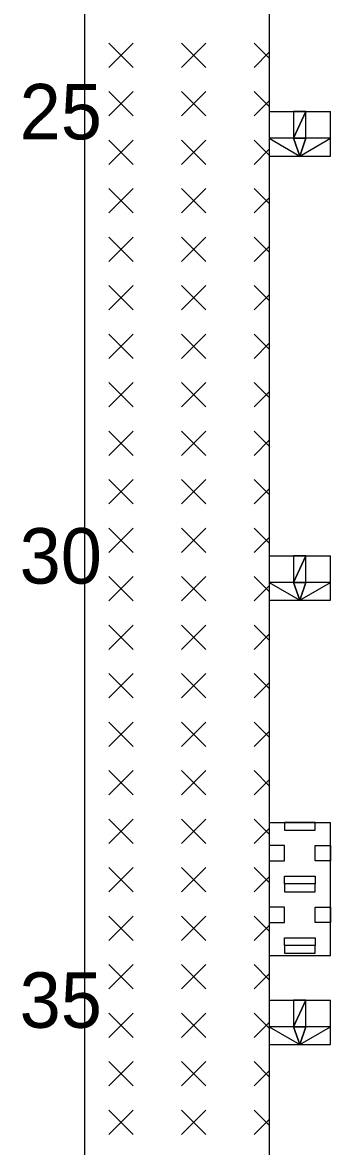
# Model space of a CAD drawing. Extents: x 2150148.6 to 2150220.1, y 143803.7 to 143875.1.
# Drawn here: x 2150202.318 to 2150203.153, y 143849.651 to 143852.692 of the extents above; entities that cross this region are included whole.
import ezdxf

# ---------------------------------------------------------------- set-up
doc = ezdxf.new("R2010")
doc.units = 0
doc.layers.add('Default', color=7, linetype='Continuous')

msp = doc.modelspace()

# ---------------------------------------------------------------- linework, layer by layer
at = {"layer": 'Default'}
for points in [[(2150202.4866, 143858.3678), (2150202.4866, 143846.4416)], [(2150202.9866, 143858.3606), (2150202.9866, 143846.4416)], [(2150202.6178, 143852.6367), (2150202.5522, 143852.5711)], [(2150202.5522, 143852.6367), (2150202.6178, 143852.5711)], [(2150202.8147, 143852.6367), (2150202.749, 143852.5711)], [(2150202.749, 143852.6367), (2150202.8147, 143852.5711)], [(2150202.9459, 143852.6367), (2150202.9866, 143852.596)], [(2150202.9866, 143852.6118), (2150202.9459, 143852.5711)], [(2150202.6178, 143852.5055), (2150202.5522, 143852.4399)], [(2150202.5522, 143852.5055), (2150202.6178, 143852.4399)], [(2150202.8147, 143852.5055), (2150202.749, 143852.4399)], [(2150202.749, 143852.5055), (2150202.8147, 143852.4399)], [(2150202.9459, 143852.5055), (2150202.9866, 143852.4648)], [(2150202.9866, 143852.4805), (2150202.9459, 143852.4399)], [(2150202.9866, 143852.4512), (2150203.1532, 143852.4512)], [(2150203.1532, 143852.331), (2150203.1532, 143852.4512)], [(2150202.6178, 143852.3742), (2150202.5522, 143852.3086)], [(2150202.5522, 143852.3742), (2150202.6178, 143852.3086)], [(2150202.8147, 143852.3742), (2150202.749, 143852.3086)], [(2150202.749, 143852.3742), (2150202.8147, 143852.3086)], [(2150202.9459, 143852.3742), (2150202.9866, 143852.3336)], [(2150202.9866, 143852.3493), (2150202.9459, 143852.3086)], [(2150202.9866, 143852.331), (2150203.1532, 143852.331)], [(2150202.6178, 143852.243), (2150202.5522, 143852.1774)], [(2150202.5522, 143852.243), (2150202.6178, 143852.1774)], [(2150202.8147, 143852.243), (2150202.749, 143852.1774)], [(2150202.749, 143852.243), (2150202.8147, 143852.1774)], [(2150202.9459, 143852.243), (2150202.9866, 143852.2023)], [(2150202.9866, 143852.2181), (2150202.9459, 143852.1774)], [(2150202.6178, 143852.1118), (2150202.5522, 143852.0462)], [(2150202.5522, 143852.1118), (2150202.6178, 143852.0462)], [(2150202.8147, 143852.1118), (2150202.749, 143852.0462)], [(2150202.749, 143852.1118), (2150202.8147, 143852.0462)], [(2150202.9459, 143852.1118), (2150202.9866, 143852.0711)], [(2150202.9866, 143852.0868), (2150202.9459, 143852.0462)], [(2150202.6178, 143851.9805), (2150202.5522, 143851.9149)], [(2150202.5522, 143851.9805), (2150202.6178, 143851.9149)], [(2150202.8147, 143851.9805), (2150202.749, 143851.9149)], [(2150202.749, 143851.9805), (2150202.8147, 143851.9149)], [(2150202.9459, 143851.9805), (2150202.9866, 143851.9399)], [(2150202.9866, 143851.9556), (2150202.9459, 143851.9149)], [(2150202.6178, 143851.8493), (2150202.5522, 143851.7837)], [(2150202.5522, 143851.8493), (2150202.6178, 143851.7837)], [(2150202.8147, 143851.8493), (2150202.749, 143851.7837)], [(2150202.749, 143851.8493), (2150202.8147, 143851.7837)], [(2150202.9459, 143851.8493), (2150202.9866, 143851.8086)], [(2150202.9866, 143851.8244), (2150202.9459, 143851.7837)], [(2150202.6178, 143851.7181), (2150202.5522, 143851.6525)], [(2150202.5522, 143851.7181), (2150202.6178, 143851.6525)], [(2150202.8147, 143851.7181), (2150202.749, 143851.6525)], [(2150202.749, 143851.7181), (2150202.8147, 143851.6525)], [(2150202.9459, 143851.7181), (2150202.9866, 143851.6774)], [(2150202.9866, 143851.6931), (2150202.9459, 143851.6525)], [(2150202.6178, 143851.5868), (2150202.5522, 143851.5212)], [(2150202.5522, 143851.5868), (2150202.6178, 143851.5212)], [(2150202.8147, 143851.5868), (2150202.749, 143851.5212)], [(2150202.749, 143851.5868), (2150202.8147, 143851.5212)], [(2150202.9459, 143851.5868), (2150202.9866, 143851.5462)], [(2150202.9866, 143851.5619), (2150202.9459, 143851.5212)], [(2150202.6178, 143851.4556), (2150202.5522, 143851.39)], [(2150202.5522, 143851.4556), (2150202.6178, 143851.39)], [(2150202.8147, 143851.4556), (2150202.749, 143851.39)], [(2150202.749, 143851.4556), (2150202.8147, 143851.39)], [(2150202.9459, 143851.4556), (2150202.9866, 143851.4149)], [(2150202.9866, 143851.4307), (2150202.9459, 143851.39)], [(2150202.6178, 143851.3244), (2150202.5522, 143851.2588)], [(2150202.5522, 143851.3244), (2150202.6178, 143851.2588)], [(2150202.8147, 143851.3244), (2150202.749, 143851.2588)], [(2150202.749, 143851.3244), (2150202.8147, 143851.2588)], [(2150202.9459, 143851.3244), (2150202.9866, 143851.2837)], [(2150202.9866, 143851.2994), (2150202.9459, 143851.2588)], [(2150202.9866, 143851.2493), (2150203.1532, 143851.2493)], [(2150203.1532, 143851.1291), (2150203.1532, 143851.2493)], [(2150202.6178, 143851.1931), (2150202.5522, 143851.1275)], [(2150202.5522, 143851.1931), (2150202.6178, 143851.1275)], [(2150202.8147, 143851.1931), (2150202.749, 143851.1275)], [(2150202.749, 143851.1931), (2150202.8147, 143851.1275)], [(2150202.9459, 143851.1931), (2150202.9866, 143851.1525)], [(2150202.9866, 143851.1682), (2150202.9459, 143851.1275)], [(2150202.9866, 143851.1291), (2150203.1532, 143851.1291)], [(2150202.6178, 143851.0619), (2150202.5522, 143850.9963)], [(2150202.5522, 143851.0619), (2150202.6178, 143850.9963)], [(2150202.8147, 143851.0619), (2150202.749, 143850.9963)], [(2150202.749, 143851.0619), (2150202.8147, 143850.9963)], [(2150202.9459, 143851.0619), (2150202.9866, 143851.0212)], [(2150202.9866, 143851.037), (2150202.9459, 143850.9963)], [(2150202.6178, 143850.9307), (2150202.5522, 143850.8651)], [(2150202.5522, 143850.9307), (2150202.6178, 143850.8651)], [(2150202.8147, 143850.9307), (2150202.749, 143850.8651)], [(2150202.749, 143850.9307), (2150202.8147, 143850.8651)], [(2150202.9459, 143850.9307), (2150202.9866, 143850.89)], [(2150202.9866, 143850.9057), (2150202.9459, 143850.8651)], [(2150202.6178, 143850.7994), (2150202.5522, 143850.7338)], [(2150202.5522, 143850.7994), (2150202.6178, 143850.7338)], [(2150202.8147, 143850.7994), (2150202.749, 143850.7338)], [(2150202.749, 143850.7994), (2150202.8147, 143850.7338)], [(2150202.9459, 143850.7994), (2150202.9866, 143850.7588)], [(2150202.9866, 143850.7745), (2150202.9459, 143850.7338)], [(2150202.6178, 143850.6682), (2150202.5522, 143850.6026)], [(2150202.5522, 143850.6682), (2150202.6178, 143850.6026)], [(2150202.8147, 143850.6682), (2150202.749, 143850.6026)], [(2150202.749, 143850.6682), (2150202.8147, 143850.6026)], [(2150202.9459, 143850.6682), (2150202.9866, 143850.6275)], [(2150202.9866, 143850.6433), (2150202.9459, 143850.6026)], [(2150202.6178, 143850.537), (2150202.5522, 143850.4714)], [(2150202.5522, 143850.537), (2150202.6178, 143850.4714)], [(2150202.8147, 143850.537), (2150202.749, 143850.4714)], [(2150202.749, 143850.537), (2150202.8147, 143850.4714)], [(2150202.9459, 143850.537), (2150202.9866, 143850.4963)], [(2150202.9866, 143850.5281), (2150203.1532, 143850.5281)], [(2150203.1532, 143850.1676), (2150203.1532, 143850.5281)], [(2150202.9866, 143850.512), (2150202.9459, 143850.4714)], [(2150202.6178, 143850.4057), (2150202.5522, 143850.3401)], [(2150202.5522, 143850.4057), (2150202.6178, 143850.3401)], [(2150202.8147, 143850.4057), (2150202.749, 143850.3401)], [(2150202.749, 143850.4057), (2150202.8147, 143850.3401)], [(2150202.9459, 143850.4057), (2150202.9866, 143850.3651)], [(2150202.9866, 143850.3808), (2150202.9459, 143850.3401)], [(2150202.6178, 143850.2745), (2150202.5522, 143850.2089)], [(2150202.5522, 143850.2745), (2150202.6178, 143850.2089)], [(2150202.8147, 143850.2745), (2150202.749, 143850.2089)], [(2150202.749, 143850.2745), (2150202.8147, 143850.2089)], [(2150202.9459, 143850.2745), (2150202.9866, 143850.2338)], [(2150202.9866, 143850.2496), (2150202.9459, 143850.2089)], [(2150202.9866, 143850.1676), (2150203.1532, 143850.1676)], [(2150202.6178, 143850.1433), (2150202.5522, 143850.0777)], [(2150202.5522, 143850.1433), (2150202.6178, 143850.0777)], [(2150202.8147, 143850.1433), (2150202.749, 143850.0777)], [(2150202.749, 143850.1433), (2150202.8147, 143850.0777)], [(2150202.9459, 143850.1433), (2150202.9866, 143850.1026)], [(2150202.9866, 143850.1183), (2150202.9459, 143850.0777)], [(2150202.9866, 143850.0474), (2150203.1532, 143850.0474)], [(2150203.1532, 143849.9272), (2150203.1532, 143850.0474)], [(2150202.6178, 143850.012), (2150202.5522, 143849.9464)], [(2150202.5522, 143850.012), (2150202.6178, 143849.9464)], [(2150202.8147, 143850.012), (2150202.749, 143849.9464)], [(2150202.749, 143850.012), (2150202.8147, 143849.9464)], [(2150202.9459, 143850.012), (2150202.9866, 143849.9714)], [(2150202.9866, 143849.9871), (2150202.9459, 143849.9464)], [(2150202.9866, 143849.9272), (2150203.1532, 143849.9272)], [(2150202.6178, 143849.8808), (2150202.5522, 143849.8152)], [(2150202.5522, 143849.8808), (2150202.6178, 143849.8152)], [(2150202.8147, 143849.8808), (2150202.749, 143849.8152)], [(2150202.749, 143849.8808), (2150202.8147, 143849.8152)], [(2150202.9459, 143849.8808), (2150202.9866, 143849.8401)], [(2150202.9866, 143849.8559), (2150202.9459, 143849.8152)], [(2150202.6178, 143849.7496), (2150202.5522, 143849.684)], [(2150202.5522, 143849.7496), (2150202.6178, 143849.684)], [(2150202.8147, 143849.7496), (2150202.749, 143849.684)], [(2150202.749, 143849.7496), (2150202.8147, 143849.684)], [(2150202.9459, 143849.7496), (2150202.9866, 143849.7089)], [(2150202.9866, 143849.7246), (2150202.9459, 143849.684)]]:
    msp.add_lwpolyline(points, dxfattribs=at)
for points in [[(2150203.0532, 143852.3791), (2150203.0866, 143852.3791), (2150203.0866, 143852.4512), (2150203.0532, 143852.3791)], [(2150203.0532, 143852.3791), (2150203.0866, 143852.4512), (2150203.0532, 143852.4512), (2150203.0532, 143852.3791)], [(2150203.0532, 143852.3791), (2150202.9866, 143852.3791), (2150203.0699, 143852.331), (2150203.0532, 143852.3791)], [(2150203.0532, 143852.3791), (2150203.0699, 143852.331), (2150203.0866, 143852.3791), (2150203.0532, 143852.3791)], [(2150203.0699, 143852.331), (2150203.1532, 143852.3791), (2150203.0866, 143852.3791), (2150203.0699, 143852.331)], [(2150203.0532, 143851.1772), (2150203.0866, 143851.1772), (2150203.0866, 143851.2493), (2150203.0532, 143851.1772)], [(2150203.0532, 143851.1772), (2150203.0866, 143851.2493), (2150203.0532, 143851.2493), (2150203.0532, 143851.1772)], [(2150203.0532, 143851.1772), (2150202.9866, 143851.1772), (2150203.0699, 143851.1291), (2150203.0532, 143851.1772)], [(2150203.0532, 143851.1772), (2150203.0699, 143851.1291), (2150203.0866, 143851.1772), (2150203.0532, 143851.1772)], [(2150203.0699, 143851.1291), (2150203.1532, 143851.1772), (2150203.0866, 143851.1772), (2150203.0699, 143851.1291)], [(2150203.0282, 143850.5281), (2150203.0282, 143850.5073), (2150203.1116, 143850.5073), (2150203.1116, 143850.5281)], [(2150202.9866, 143850.424), (2150203.0282, 143850.424), (2150203.0282, 143850.4656), (2150202.9866, 143850.4656)], [(2150203.1532, 143850.424), (2150203.1116, 143850.424), (2150203.1116, 143850.4656), (2150203.1532, 143850.4656)], [(2150203.0282, 143850.3615), (2150203.0282, 143850.3823), (2150203.1116, 143850.3823), (2150203.1116, 143850.3615)], [(2150203.0282, 143850.3615), (2150203.0282, 143850.3406), (2150203.1116, 143850.3406), (2150203.1116, 143850.3615)], [(2150202.9866, 143850.2573), (2150203.0282, 143850.2573), (2150203.0282, 143850.299), (2150202.9866, 143850.299)], [(2150203.1532, 143850.2573), (2150203.1116, 143850.2573), (2150203.1116, 143850.299), (2150203.1532, 143850.299)], [(2150203.0282, 143850.1948), (2150203.0282, 143850.2157), (2150203.1116, 143850.2157), (2150203.1116, 143850.1948)], [(2150203.0282, 143850.1948), (2150203.0282, 143850.174), (2150203.1116, 143850.174), (2150203.1116, 143850.1948)], [(2150203.0532, 143849.9753), (2150203.0866, 143849.9753), (2150203.0866, 143850.0474), (2150203.0532, 143849.9753)], [(2150203.0532, 143849.9753), (2150203.0866, 143850.0474), (2150203.0532, 143850.0474), (2150203.0532, 143849.9753)], [(2150203.0532, 143849.9753), (2150202.9866, 143849.9753), (2150203.0699, 143849.9272), (2150203.0532, 143849.9753)], [(2150203.0532, 143849.9753), (2150203.0699, 143849.9272), (2150203.0866, 143849.9753), (2150203.0532, 143849.9753)], [(2150203.0699, 143849.9272), (2150203.1532, 143849.9753), (2150203.0866, 143849.9753), (2150203.0699, 143849.9272)]]:
    msp.add_lwpolyline(points, close=True, dxfattribs=at)

# ---------------------------------------------------------------- texts
for s, p in [('25', (2150202.3104, 143852.3762)), ('30', (2150202.3104, 143851.1743)), ('35', (2150202.3104, 143849.9724))]:
    msp.add_text(s, height=0.15, dxfattribs=at).set_placement(p)

doc.saveas('drawing.dxf')
